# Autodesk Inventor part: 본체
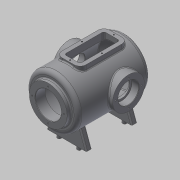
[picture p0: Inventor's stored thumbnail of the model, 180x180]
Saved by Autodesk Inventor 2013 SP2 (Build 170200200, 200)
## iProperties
Created: 2016-02
Part Number: 본체
Material: 일반
Document SubType Name: Modeling
Designer: mduedu
Density: 1 g/cm^3
Author: mduedu
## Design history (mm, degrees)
sketch "스케치2"
  geometry: L1 (0, 100)-(0, -100); L2 (65, -75.993)-(65, 100); L3 (65, 100)-(0, 100); A1 r 100 centre (0, 0) between (0, -100) and (65, -75.993); 2 further points
  constraints: 6 end point, 2 midpoint, 2 point on circle, 1 centre point, 1 coincident, 1 horizontal, 1 parallel, 1 vertical
  dimensions: "d3" = 200 distance of L1.start L1.end; "d5" = 130 diameter of L2 L1; "d6" = 100 radius of A1
revolve "회전1" sketch "스케치2" stored, may be unused: angle "d7" = 90 deg
sketch "스케치3"
  geometry: C1 r 47.5 at (0, 0); 1 further point
  constraints: 1 centre point, 1 coincident
  dimensions: "d8" = 95 diameter of C1
extrude "돌출2" join sketch "스케치3" distance "d10" = 10; taper "d11" = 0 deg
sketch "스케치5"
  geometry: L1 (47.5, 110)-(47.5, 100) reference; L2 (47.5, 100)-(65, 100) reference; L3 (65, 100)-(65, -75.993) reference; L4 (-65, -75.993)-(-65, 100) reference; L5 (-65, 100)-(-47.5, 100) reference; L6 (-47.5, 100)-(-47.5, 110) reference; L7 (-47.5, 110)-(47.5, 110) reference; L8 (55, 85)-(55, -71.239); L9 (0, 85)-(55, 85); L10 (0, 85)-(0, -90); A1 r 100 centre (0, 0) between (0, -100) and (65, -75.993) reference; A2 r 100 centre (0, 0) between (-65, -75.993) and (0, -100) reference; A3 r 90 centre (0, 0) between (0, -90) and (55, -71.239); 1 further point
  constraints: 6 end point, 2 point on circle, 1 centre point, 1 parallel, 1 perpendicular, 1 point on line, 1 vertical
  dimensions: "d13" = 10 distance between parallel lines of L3 L8; "d14" = 10 radial gap between concentric circles of A3 A1; "d15" = 15 distance between parallel lines of L9 L2
revolve "회전2" sketch "스케치5" stored, may be unused: angle "d16" = 90 deg
hole "구멍1" diameter "d19" = 65; stored, may be unused: countersink angle "d23" = 90 deg, drill point angle "d25" = 118 deg; dims "d17" = 10, "d18" = 10, "d20" = 6, "d21" = 4, "d22" = 2, "d24" = 8
node "작업 평면1"
sketch "스케치6"
  geometry: L1 (47.5, 110)-(-47.5, 110) reference; C1 r 40 at (0, -17); 1 further point
  constraints: 1 centre point, 1 vertical alignment
  dimensions: "d27" = 80 diameter of C1; "d29" = 127 distance from line of C1.centre L1
extrude "돌출3" join sketch "스케치6" stored distance "d30" = 10; taper "d31" = 0 deg
hole "구멍2" diameter "d34" = 42; stored, may be unused: countersink angle "d38" = 90 deg, drill point angle "d40" = 118 deg; dims "d32" = 10, "d33" = 10, "d35" = 6, "d36" = 52, "d37" = 18, "d39" = 8
sketch "스케치7" dims "d41" = 65
  geometry: C1 r 40 at (0, 0) reference; 3 further points
  constraints: 2 vertical alignment, 1 coincident, 2 other
hole "구멍3" sketch "스케치7" at (0, 32.5) diameter "d43" = 3.242; stored, may be unused: countersink angle "d47" = 90 deg, drill point angle "d49" = 118 deg; dims "d44" = 11, "d45" = 13, "d46" = 18, "d48" = 13
sketch "스케치8" dims "d53" = 80
  geometry: 3 further points
  constraints: 2 vertical alignment, 1 coincident, 2 other
hole "구멍4" sketch "스케치8" at (0, 40) diameter "d56" = 3.242; stored, may be unused: countersink angle "d60" = 90 deg, drill point angle "d62" = 118 deg; dims "d57" = 11, "d58" = 13, "d59" = 18, "d61" = 13
fillet "모깎기1" dims "d66" = 10
fillet "모깎기2" dims "d67" = 3
fillet "모깎기3" dims "d68" = 0.3
chamfer "모따기1" distance "d69" = 1; stored, may be unused: second distance "d70" = 2, angle "d71" = 45 deg
node "작업 평면5"
sketch "스케치10"
  geometry: L1 (-50, -64)-(50, -64); L2 (50, -64)-(50, -50); L3 (50, -50)-(-50, -50); L4 (-50, -50)-(-50, -64); L5 (-50, 0)-(50, 0); L6 (-50, 64)-(50, 64); L7 (50, 64)-(50, 50); L8 (50, 50)-(-50, 50); L9 (-50, 50)-(-50, 64); 2 further points
  constraints: 18 end point, 4 symmetric about line, 2 parallel, 2 perpendicular, 1 coincident, 1 horizontal, 1 midpoint
  dimensions: "d80" = 14 distance of L3.end L1.start; "d82" = 100 distance of L1.start L1.end; "d130" = 50 horizontal distance of L3.end point (0, 0); "d131" = 50 horizontal distance of L3.end point (0, 0); "d132" = 100 distance of L5.start L5.end
extrude "돌출5" join sketch "스케치10" stored distance "d84" = 10; taper "d85" = 0 deg
feature "면 기울기3" dims angle "d135" = 20 deg
sketch "스케치11"
  geometry: L1 (-85, -50)-(-85, 50); L2 (-65, 90)-(-65, -71.239) reference; L3 (-100, -50)-(-41.533, -50) reference; L4 (-100, 50)-(-41.533, 50) reference; 1 further point
  constraints: 2 end point, 2 point on line
  dimensions: "d87" = 20 distance between parallel lines of L1 L2
feature "리브1" sketch "스케치11" dims "d88" = 1, "d89" = 8, "d90" = 0, "d91" = 0, "d92" = 1, "d93" = 1
fillet "모깎기5" dims "d103" = 3
fillet "모깎기6" dims "d105" = 3
node "작업 평면6"
sketch "스케치15"
  geometry: L1 (-30, 60)-(30, 60); L2 (30, 60)-(30, -60); L3 (30, -60)-(-30, -60); L4 (-30, -60)-(-30, 60); 2 further points
  constraints: 8 end point, 2 parallel, 1 horizontal, 1 midpoint, 1 perpendicular, 1 vertical alignment
  dimensions: "d110" = 60 distance of L2.end L3.end; "d112" = 60 distance from line of L3 point (0, 0); "d113" = 120 distance of L1.end L2.end
extrude "돌출8" join sketch "스케치15" stored distance "d114" = 10; taper "d115" = 0 deg
fillet "모깎기7" dims "d116" = 15
sketch "스케치16"
  geometry: L1 (-30, -45)-(-30, 45) reference; L2 (30, 45)-(30, -45) reference; L3 (-15, 60)-(15, 60) reference; L4 (15, -60)-(-15, -60) reference; L5 (-20, -45)-(-20, 45); L6 (-15, 50)-(15, 50); L7 (20, 45)-(20, -45); L8 (15, -50)-(-15, -50); A1 r 15 centre (-15, -45) between (-30, -45) and (-15, -60) reference; A2 r 15 centre (-15, 45) between (-15, 60) and (-30, 45) reference; A3 r 15 centre (15, 45) between (30, 45) and (15, 60) reference; A4 r 15 centre (15, -45) between (15, -60) and (30, -45) reference; A5 r 5 centre (-15, -45) between (-20, -45) and (-15, -50); A6 r 5 centre (-15, 45) between (-15, 50) and (-20, 45); A7 r 5 centre (15, 45) between (20, 45) and (15, 50); A8 r 5 centre (15, -45) between (15, -50) and (20, -45)
  constraints: 8 end point, 8 point on circle, 4 centre point, 7 other
  dimensions: "d137" = 10 distance between parallel lines of L5 L1
extrude "돌출9" cut sketch "스케치16" stored distance "d118" = 10; taper "d119" = 0 deg
fillet "모깎기8" dims "d120" = 3
sketch "스케치17"
  geometry: L1 (-30, -45)-(-30, 45) reference; L2 (30, 45)-(30, -45) reference; L3 (-20, 45)-(-20, -45) reference; L4 (-15, -50)-(15, -50) reference; L5 (20, -45)-(20, 45) reference; L6 (15, 50)-(-15, 50) reference; L7 (-15, 60)-(15, 60) reference; L8 (15, -60)-(-15, -60) reference; L9 (15, 55)-(-15, 55); L10 (-25, 45)-(-25, -45); L11 (-15, -55)-(15, -55); L12 (25, -45)-(25, 45); A1 r 5 centre (-15, 45) between (-15, 50) and (-20, 45) reference; A2 r 5 centre (-15, -45) between (-20, -45) and (-15, -50) reference; A3 r 5 centre (15, -45) between (15, -50) and (20, -45) reference; A4 r 5 centre (15, 45) between (20, 45) and (15, 50) reference; A5 r 15 centre (-15, 45) between (-15, 60) and (-30, 45) reference; A6 r 15 centre (15, 45) between (30, 45) and (15, 60) reference; A7 r 15 centre (15, -45) between (15, -60) and (30, -45) reference; A8 r 15 centre (-15, -45) between (-30, -45) and (-15, -60) reference; A9 r 10 centre (-15, 45) between (-15, 55) and (-25, 45); A10 r 10 centre (-15, -45) between (-25, -45) and (-15, -55); A11 r 10 centre (15, -45) between (15, -55) and (25, -45); A12 r 10 centre (15, 45) between (25, 45) and (15, 55); 4 further points
  constraints: 8 end point, 8 point on circle, 4 centre point, 4 midpoint, 7 other
  dimensions: "d138" = 5 distance between parallel lines of L9 L7
hole "구멍5" sketch "스케치17" at (0, 55), (25, 0), (0, -55), (-25, 0) diameter "d122" = 3.242; stored, may be unused: countersink angle "d126" = 90 deg, drill point angle "d128" = 118 deg; dims "d123" = 9, "d124" = 13, "d125" = 18, "d127" = 11
fillet "모깎기9" dims "d129" = 3
sketch "스케치18"
  geometry: L1 (-46.807, 50)-(46.807, 50) reference; L2 (50, 53)-(50, 61) reference; L3 (46.807, 64)-(-46.807, 64) reference; L4 (-50, 61)-(-50, 53) reference; L5 (-50, 57)-(50, 57); L6 (0, 64)-(0, 50); C1 r 5 at (-25, 57); C2 r 5 at (25, 57); 5 further points; 4 other entities
  constraints: 4 end point, 4 midpoint, 2 centre point, 1 point on line, 1 symmetric about line, 5 other
  dimensions: "d139" = 10 diameter of C1; "d141" = 25 distance from line of L6 C1.centre; "d147" = 57 vertical distance of C2.centre point (0, 0) (derived)
extrude "돌출10" join sketch "스케치18" distance "d142" = 10; taper "d143" = 0 deg
chamfer "모따기2" distance "d144" = 1; stored, may be unused: second distance "d145" = 2, angle "d146" = 45 deg
node "작업 평면7"
fillet "모깎기10" dims "d148" = 0.5
node "솔리드2"
pattern_circular "원형 패턴1" dims angle "d51" = 360 deg
mirror "대칭1"
pattern_circular "원형 패턴2" dims angle "d64" = 360 deg
mirror "대칭2"
node "투영된 루프1"
node "절단 모서리 투영1"
node "절단 모서리 투영2"
node "절단 모서리 투영3"
other parameters: "d26" = 75
